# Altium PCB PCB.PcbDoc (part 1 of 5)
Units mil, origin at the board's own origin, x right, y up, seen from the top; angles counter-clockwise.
Board outline 6700 x 6500 mil, 2 copper layers (Top Layer, Bottom Layer); 203 components, 278 nets, 1296 pads, 461 vias.
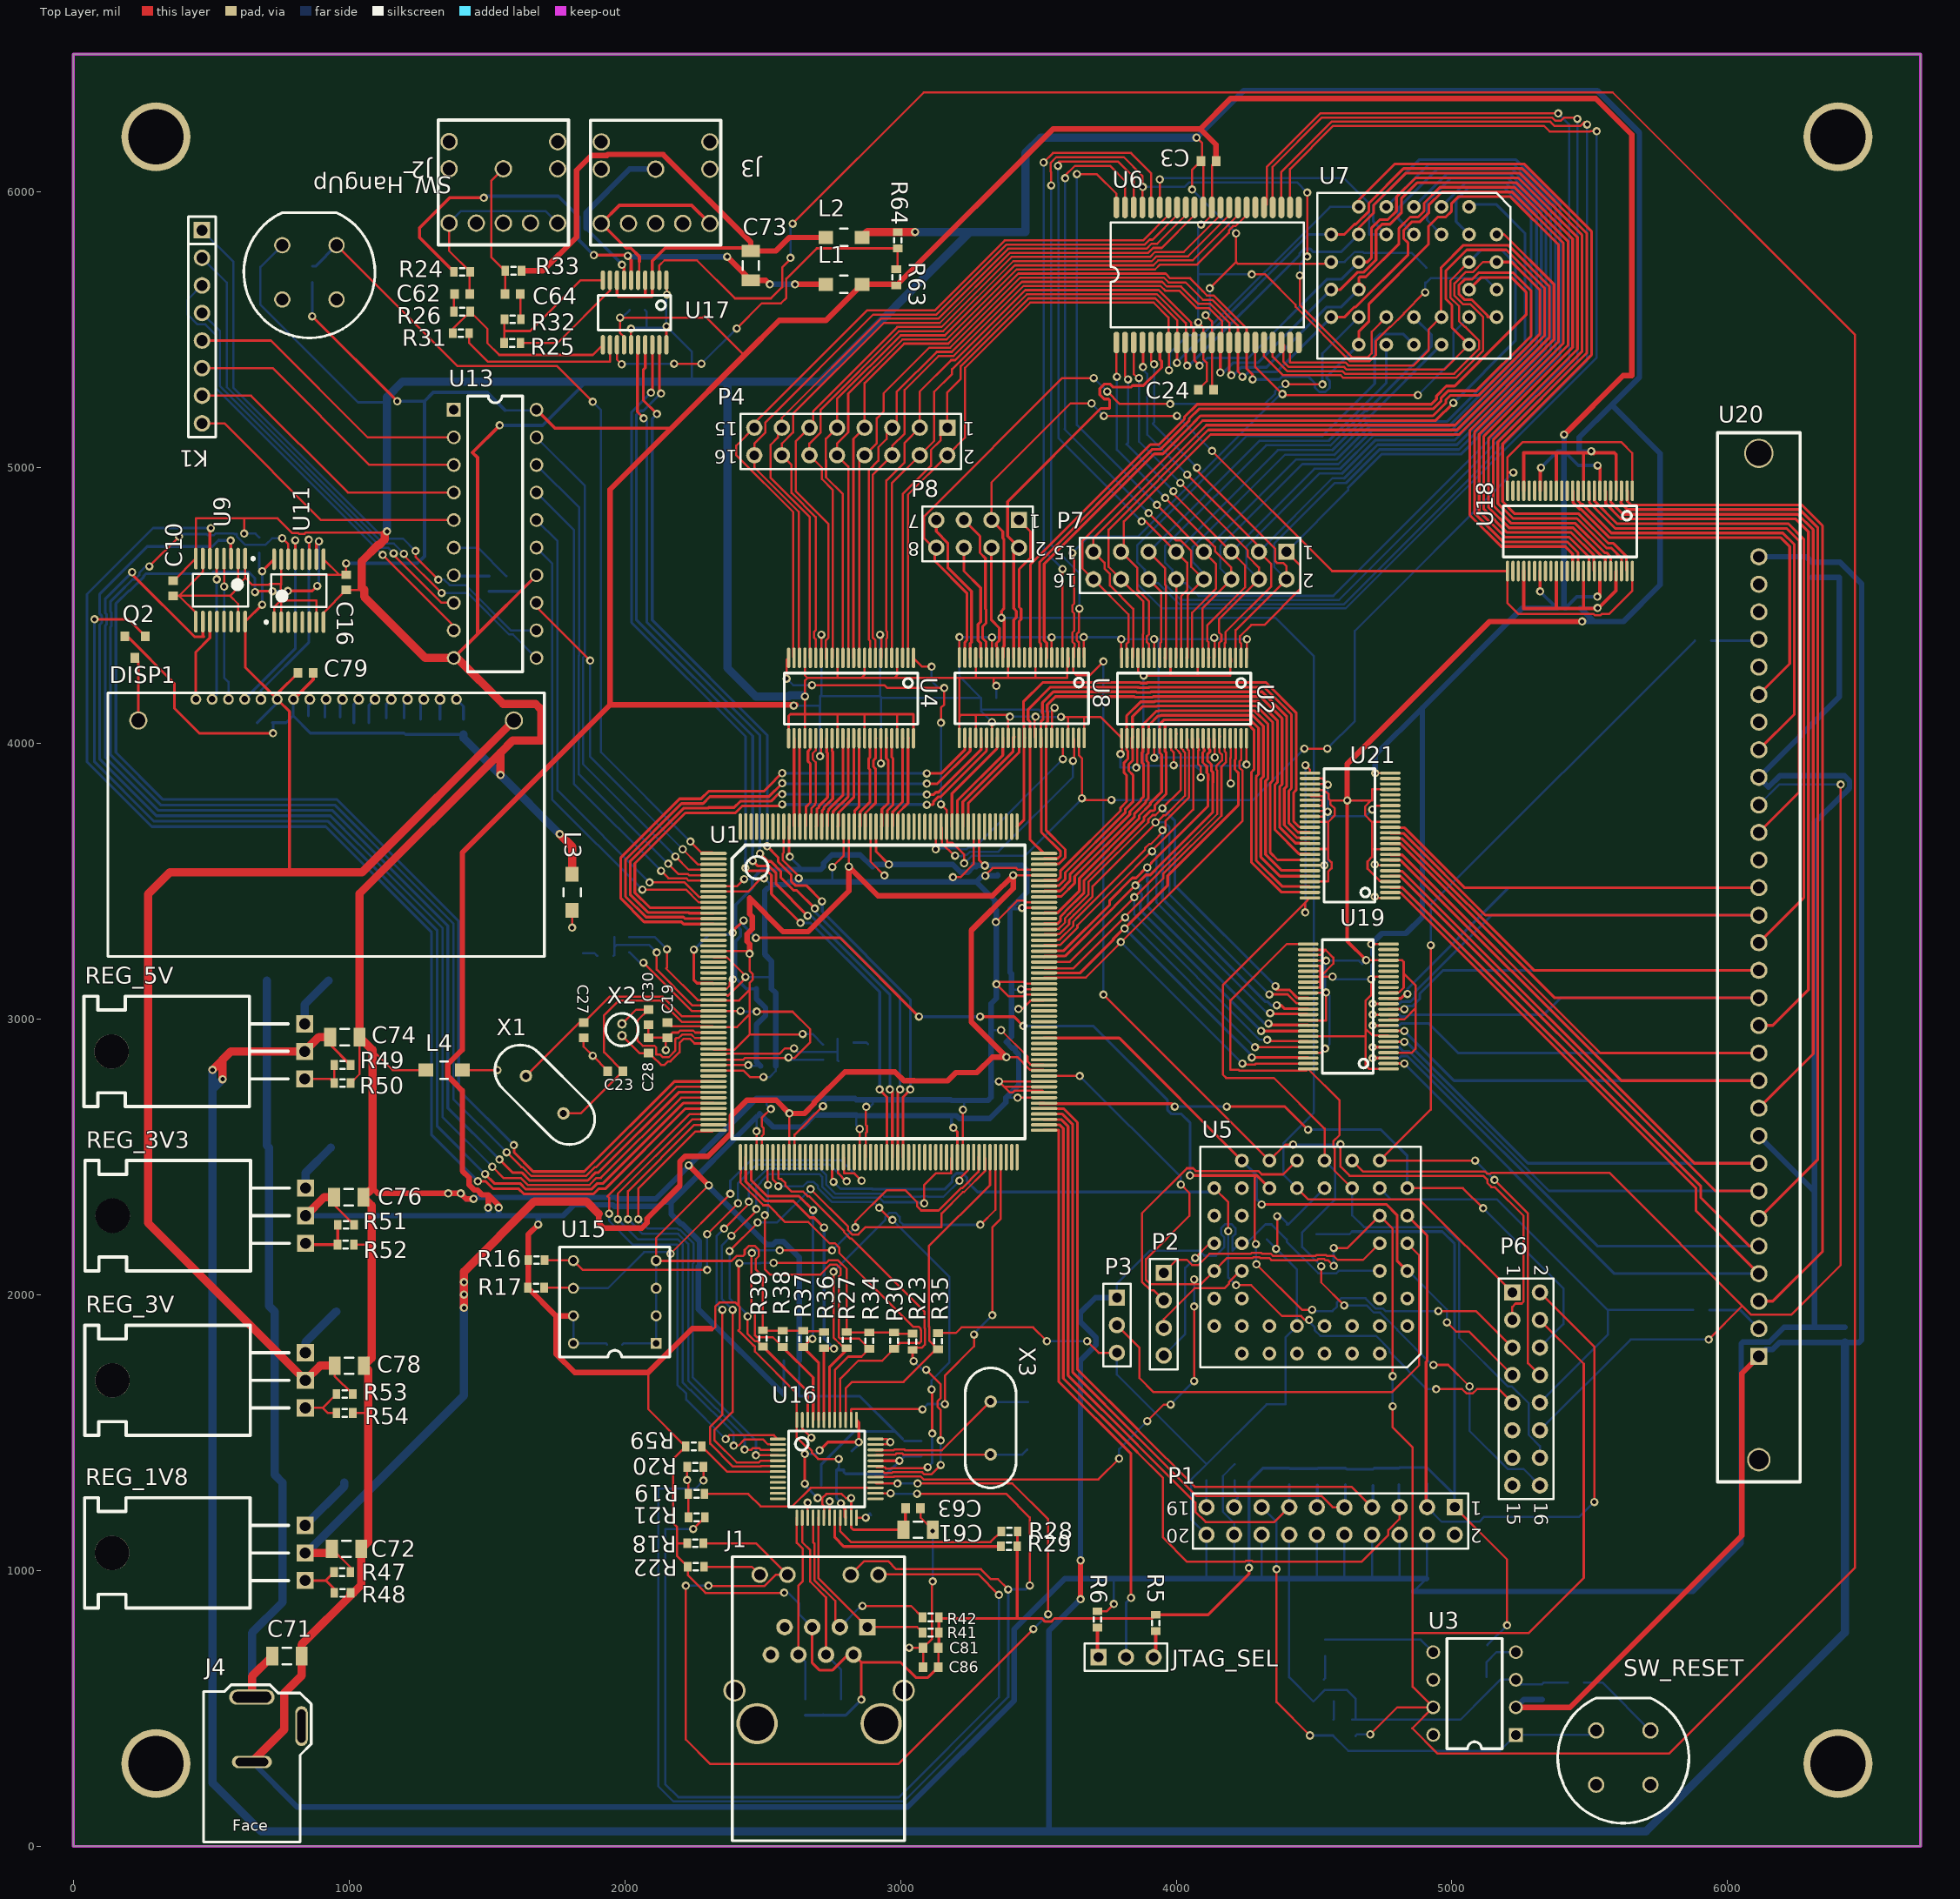
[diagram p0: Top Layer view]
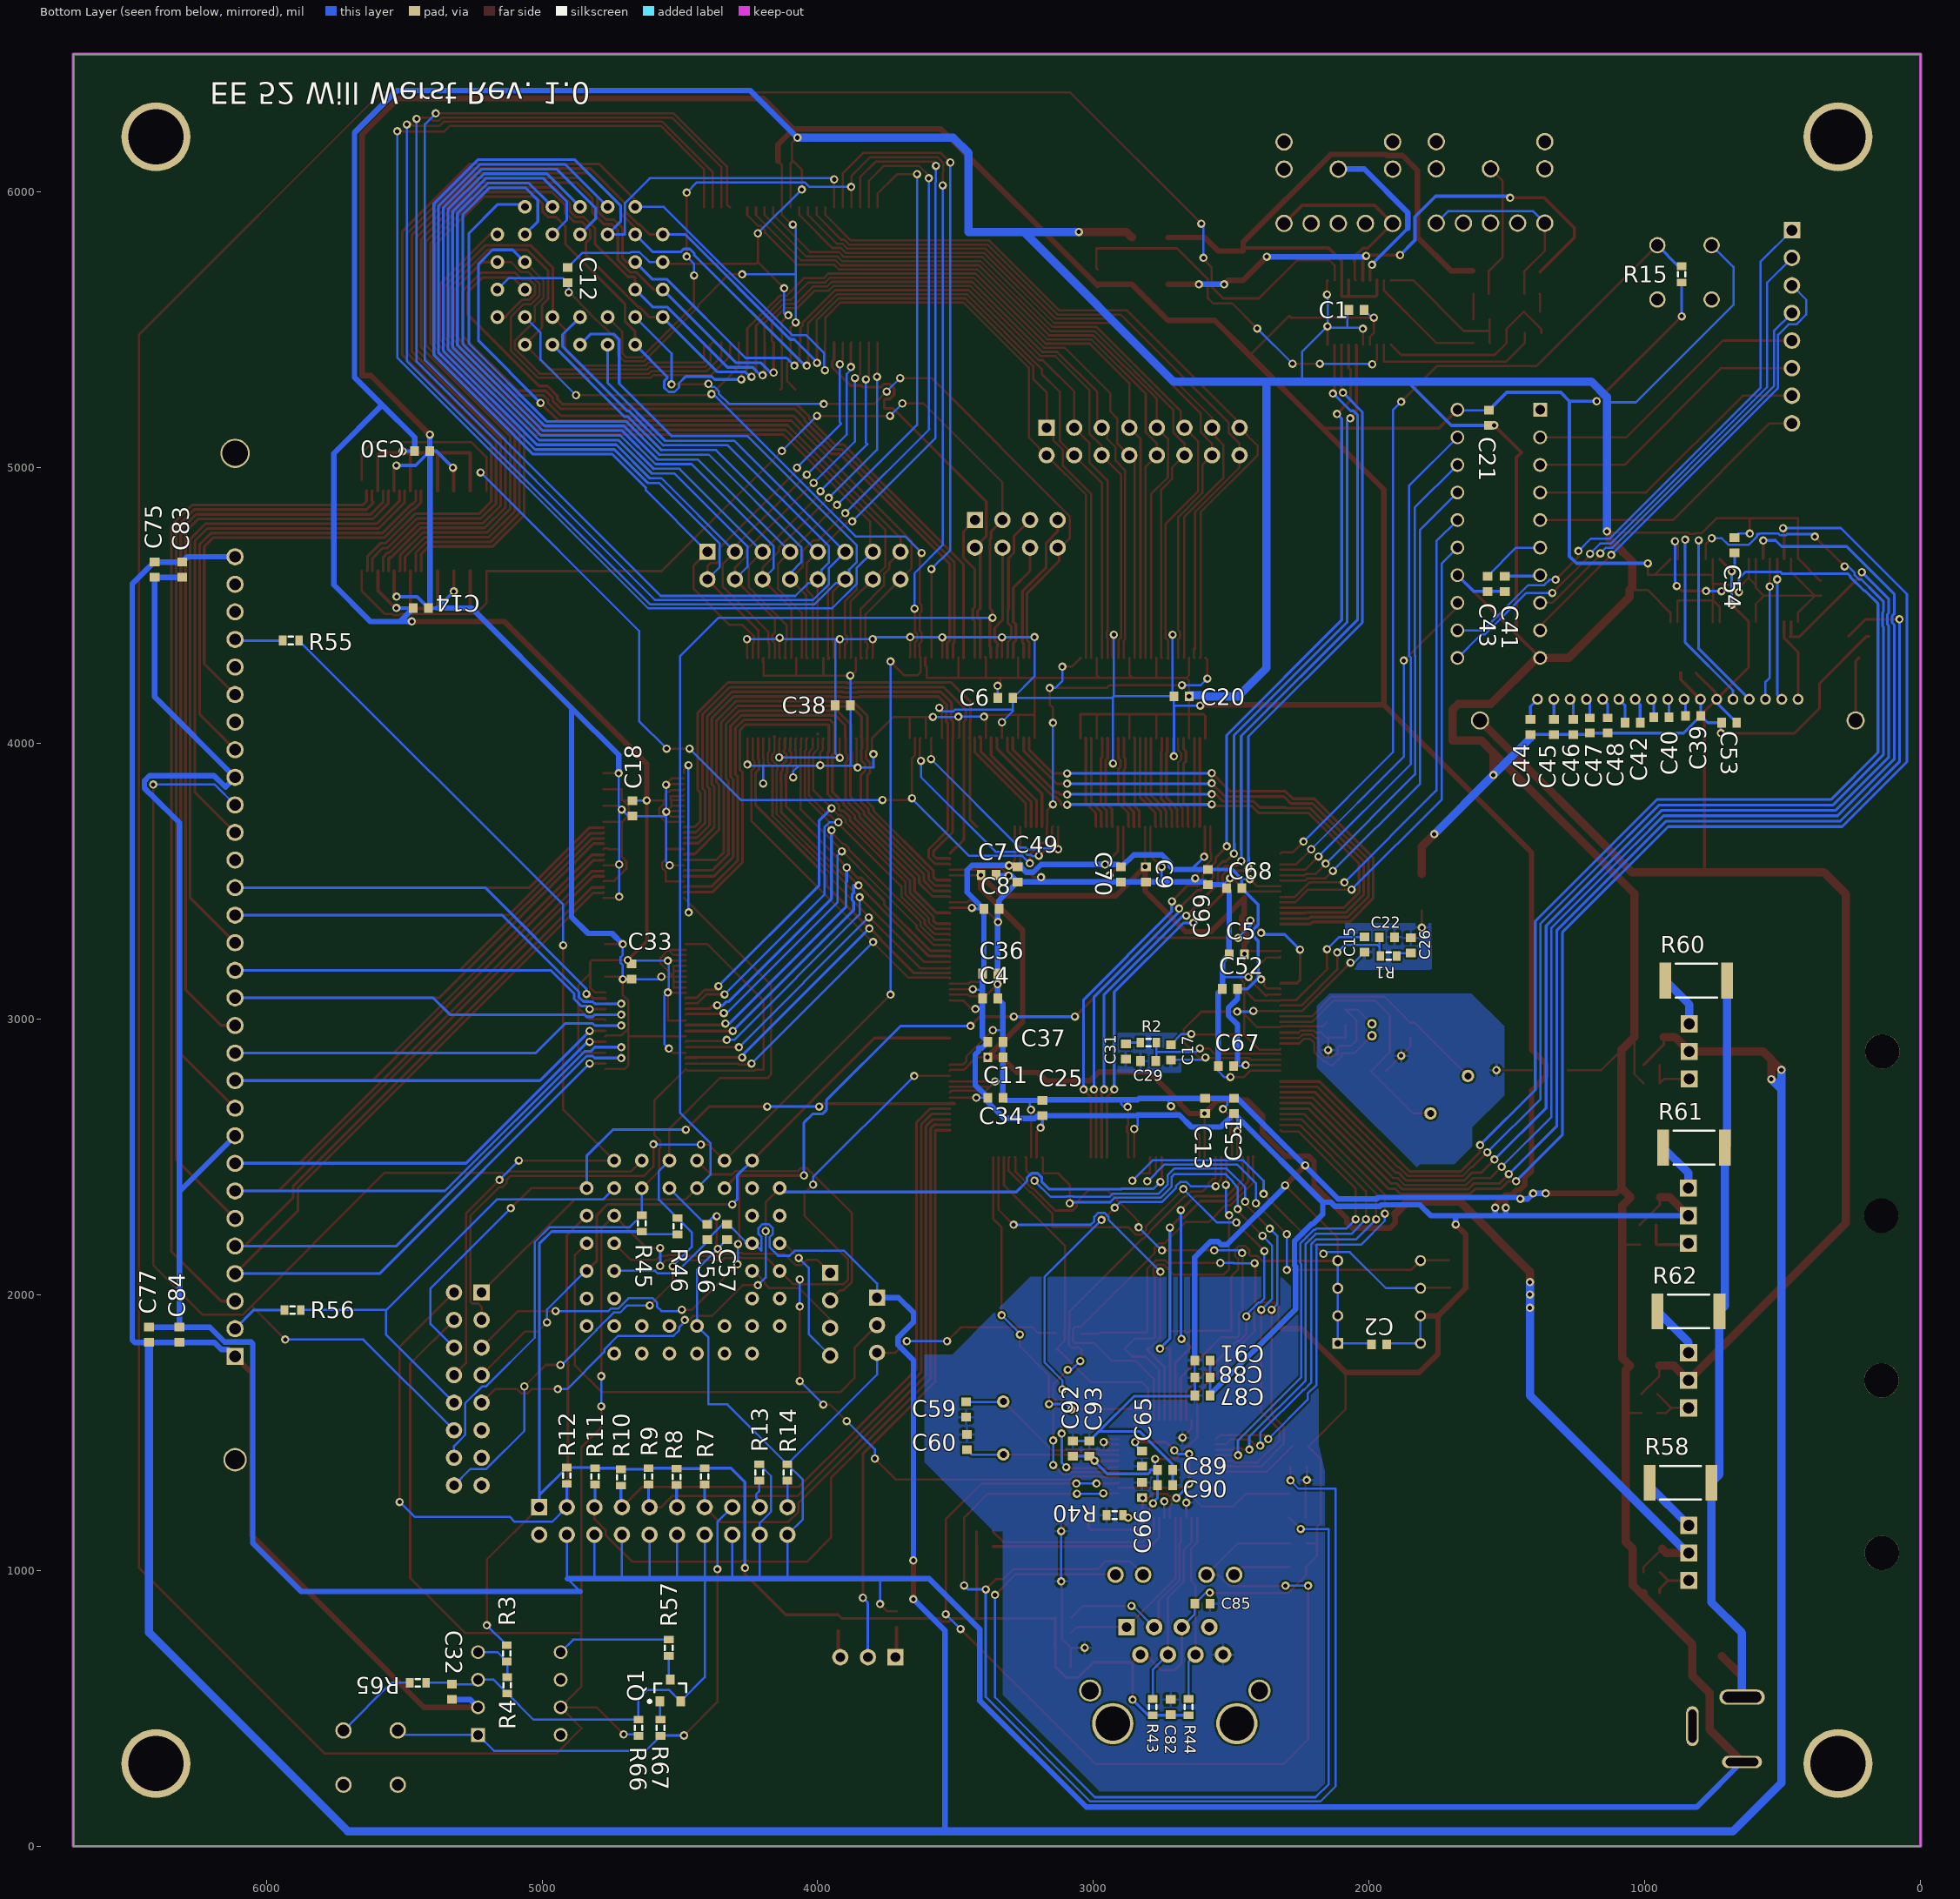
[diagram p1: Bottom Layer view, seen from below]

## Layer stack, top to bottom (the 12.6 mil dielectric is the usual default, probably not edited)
Top Solder: solder mask 0.4, Solder Resist, Dk 3.5
Top Layer: signal copper 1.4
Dielectric 1: dielectric 12.6, FR-4, Dk 4.8
Bottom Layer: signal copper 1.4
Bottom Solder: solder mask 0.4, Solder Resist, Dk 3.5

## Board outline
0,0 0,6500 6700,6500 6700,0

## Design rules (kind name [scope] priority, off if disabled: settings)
Clearance [All] p1: gap=7 ignorepadtopadclearanceinfootprint=FALSE except(0: Arc-Hole Track-Hole SMDPad-Hole THPad-Hole Via-Hole Fill-Hole Poly-Hole Region-Hole Text-Hole)
HoleSize [All] p1: absolutevalues=TRUE maxlimit=250 minlimit=10 maxpercent=80.000 minpercent=20.000
MinimumAnnularRing [All] p1: minimumring=7
MinimumSolderMaskSliver [All] p1 off: minsoldermaskwidth=3
PlaneConnect [All] p1: planeconnectstyle=Relief reliefexpansion=15 reliefentries=4 reliefconductorwidth=10 reliefairgap=10
PolygonConnect [All] p1: connectstyle=Relief reliefconductorwidth=10 reliefentries=4 polygonreliefangle="90 Angle" airgapwidth=10
RoutingCorners [All] p1: cornerstyle=45-Degree minsetback=10 maxsetback=100
RoutingTopology [All] p1: topology=Daisy_Balanced
RoutingVias [All] p1: holewidth=16 width=30 viastyle="Through Hole" minholewidth=16 minwidth=30 maxholewidth=28 maxwidth=50
SilkToSilkClearance [All] p1: silktosilkclearance=6
SilkToSolderMaskClearance [IsPad] p1 off: minsilkscreentomaskgap=3 clearancetoexposedcopper=TRUE
SolderMaskExpansion [All] p1: expansion=2.5
Width [All] p1: maxlimit=30 minlimit=7 preferedwidth=8
23 further rules are at their usual default settings.

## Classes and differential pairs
net class A_3V3_BUF_[0..19]: A_3V3_BUF_0 A_3V3_BUF_1 A_3V3_BUF_2 A_3V3_BUF_3 A_3V3_BUF_4 A_3V3_BUF_5 A_3V3_BUF_6 A_3V3_BUF_7 A_3V3_BUF_8 A_3V3_BUF_9 A_3V3_BUF_10 A_3V3_BUF_11 A_3V3_BUF_12 A_3V3_BUF_13 A_3V3_BUF_14 A_3V3_BUF_15 A_3V3_BUF_16 A_3V3_BUF_17 A_3V3_BUF_18 A_3V3_BUF_19
net class ADDR[16..19]: ADDR0 ADDR1 ADDR2 ADDR3 ADDR4 ADDR5 ADDR6 ADDR7 ADDR8 ADDR9 ADDR10 ADDR11 ADDR12 ADDR13 ADDR14 ADDR15 ADDR16 ADDR17 ADDR18 ADDR19
net class D_3V3B[0..15]: D_3V3B0 D_3V3B1 D_3V3B2 D_3V3B3 D_3V3B4 D_3V3B5 D_3V3B6 D_3V3B7 D_3V3B8 D_3V3B9 D_3V3B10 D_3V3B11 D_3V3B12 D_3V3B13 D_3V3B14 D_3V3B15
net class DATA[0..15]: DATA0 DATA1 DATA2 DATA3 DATA4 DATA5 DATA6 DATA7 DATA8 DATA9 DATA10 DATA11 DATA12 DATA13 DATA14 DATA15
net class NCS3V3B[0..7]: NCS3V3B0 NCS3V3B1 NCS3V3B2 NCS3V3B3 NCS3V3B4 NCS3V3B5 NCS3V3B6 NCS3V3B7
net class NCS[4..7]: NCS0 NCS1 NCS2 NCS3 NCS4 NCS5 NCS6 NCS7

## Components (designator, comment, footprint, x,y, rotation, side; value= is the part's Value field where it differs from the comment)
C1 "" 1608[0603] 2046,5572 r0 bottom value=0.1uF
C2 "" 1608[0603] 1964,1820 r0 bottom value=0.1uF
C3 "" 1608[0603] 4117,6112 r180 top value=0.1uF
C4 "" 1608[0603] 3375,3075 r180 bottom value=0.1uF
C5 "" 1608[0603] 2480,3235 r180 bottom value=0.1uF
C6 "" 1608[0603] 3320,4165 r0 bottom value=0.1uF
C7 "" 1608[0603] 3380,3523 r0 bottom value=0.1uF
C8 "" 1608[0603] 3370,3400 r180 bottom value=0.1uF
C9 "" 1608[0603] 2810,3525 r90 bottom value=0.1uF
C10 "" 1608[0603] 362,4563 r90 top value=0.1uF
C11 "" 1608[0603] 3356,2861 r0 bottom value=0.1uF
C12 "" 1608[0603] 4907,5698.44 r90 bottom value=0.1uF
C13 "" 1608[0603] 2595,2685 r270 bottom value=0.1uF
C14 "" 1608[0603] 5439,4491 r0 bottom value=0.1uF
C15 "" 1608[0603] 2017,3270.56 r90 bottom value=0.1uF
C16 "" 1608[0603] 990,4584 r270 top value=0.1uF
C17 "" 1608[0603] 2719,2880 r90 bottom value=0.1uF
C18 "" 1608[0603] 4672,3764 r90 bottom value=0.1uF
C19 "" 1608[0603] 2155,2960 r90 top value=0.1uF
C20 "" 1608[0603] 2681,4171 r180 bottom value=0.1uF
C21 "" 1608[0603] 1566,5181 r270 bottom value=0.1uF
C22 "" 1608[0603] 1935.67,3297 r180 bottom value=1nF
C23 "" 1608[0603] 1966,2811 r180 top value=30pF
C24 "" 1608[0603] 4108,5283 r0 top value=0.1uF
C25 "" 1608[0603] 3185,2677.44 r90 bottom value=0.1uF
C26 "" 1608[0603] 1849,3267 r90 bottom value=10nF
C27 "" 1608[0603] 1851,2960 r270 top value=30pF
C28 "" 1608[0603] 2086,2904 r90 top value=16pF
C29 "" 1608[0603] 2802,2848 r0 bottom value=1nF
C30 "" 1608[0603] 2086,3007 r270 top value=16pF
C31 "" 1608[0603] 2882,2882 r270 bottom value=10nF
C32 "" 1608[0603] 5327,560 r90 bottom value=0.1uF
C33 "" 1608[0603] 4675,3172.44 r90 bottom value=0.1uF
C34 "" 1608[0603] 3355,2715 r180 bottom value=0.1uF
C36 "" 1608[0603] 3375,3165 r180 bottom value=0.1uF
C37 "" 1608[0603] 3356,2917 r180 bottom value=0.1uF
C38 "" 1608[0603] 3909,4138 r180 bottom value=0.1uF
C39 "" 1608[0603] 825,4100 r180 bottom value=1uF
C40 "" 1608[0603] 940,4095 r180 bottom value=1uF
C41 "" 1608[0603] 1508,4579 r270 bottom value=1uF
C42 "" 1608[0603] 1045,4075 r180 bottom value=1uF
C43 "" 1608[0603] 1571,4579 r270 bottom value=0.1uF
C44 "" 1608[0603] 1415,4060 r90 bottom value=1uF
C45 "" 1608[0603] 1330,4060 r90 bottom value=1uF
C46 "" 1608[0603] 1260,4060 r90 bottom value=1uF
C47 "" 1608[0603] 1200,4065 r90 bottom value=1uF
C48 "" 1608[0603] 1135,4065 r90 bottom value=1uF
C49 "" 1608[0603] 3275,3525 r270 bottom value=0.1uF
C50 "" 1608[0603] 5434,5060 r0 bottom value=0.1uF
C51 "" 1608[0603] 2490,2685 r90 bottom value=0.1uF
C52 "" 1608[0603] 2505,3110 r0 bottom value=0.1uF
C53 "" 1608[0603] 695,4075 r0 bottom value=0.1uF
C54 "" 1608[0603] 675,4719 r90 bottom value=0.1uF
C56 "" 1608[0603] 4401,2228 r90 bottom value=0.1uF
C57 "" 1608[0603] 4329,2228 r270 bottom value=0.1uF
C59 "" 1608[0603] 3462,1584 r270 bottom value=30pF
C60 "" 1608[0603] 3459,1466 r90 bottom value=30pF
C61 "Tant" C1206 3064,1148 r0 top value=10uF
C62 "" 1608[0603] 1410,5630 r180 top value=0.22uF
C63 "" 1608[0603] 3045.56,1226 r0 top value=0.1uF
C64 "" 1608[0603] 1594,5630 r0 top value=0.22uF
C65 "" 1608[0603] 2824,1406 r270 bottom value=0.1uF
C66 "" 1608[0603] 2824,1292 r90 bottom value=0.1uF
C67 "" 1608[0603] 2520,2830 r0 bottom value=0.1uF
C68 "" 1608[0603] 2490,3475 r0 bottom value=0.1uF
C69 "" 1608[0603] 2585,3515 r270 bottom value=0.1uF
C70 "" 1608[0603] 2900,3525 r270 bottom value=0.1uF
C71 "" C1206 775,690 r180 top value=10uF
C72 "" C1206 991,1079 r180 top value=10uF
C73 "" C1206 2457,5733 r270 top value=10uF
C74 "" C1206 985,2935 r180 top value=10uF
C75 "" 1608[0603] 6405,4630 r270 bottom value=1uF
C76 "" C1206 999,2354 r180 top value=10uF
C77 "" 1608[0603] 6425,1855 r90 bottom value=1uF
C78 "" C1206 1001,1743 r180 top value=10uF
C79 "" 1608[0603] 843,4256 r180 top value=1uF
C81 "" 1608[0603] 3110,720 r180 top value=0.1uF
C82 "" 1608[0603] 2720,505 r90 bottom value=0.1uF
C83 "" 1608[0603] 6305,4630 r270 bottom value=0.01uF
C84 "" 1608[0603] 6315,1855 r90 bottom value=0.01uF
C85 "" 1608[0603] 2605,880 r180 bottom value=0.1uF
C86 "" 1608[0603] 3110,650 r180 top value=0.1uF
C87 "" 1608[0603] 2605,1635 r0 bottom value=0.1uF
C88 "" 1608[0603] 2605,1700 r0 bottom value=0.01uF
C89 "" 1608[0603] 2740,1365 r180 bottom value=0.1uF
C90 "" 1608[0603] 2740,1310 r180 bottom value=0.1uF
C91 "" 1608[0603] 2605,1762 r0 bottom value=1uF
C92 "" 1608[0603] 3075,1442.44 r90 bottom value=0.1uF
C93 "" 1608[0603] 3015,1442.44 r90 bottom value=0.01uF
DISP1 "Newhaven Display NHD-C12832A1Z-FSW-FBW-3V3" PCB-1539121-1 917.06,4160 r180 top locked
J1 "SI-50170" SI51070 2530,695 r0 top
J2 "Speaker" SJ1-352 1363.15,5887.15 r90 top locked
J3 "Microphone" SJ1-352 1915.15,5886 r90 top locked
J4 "Power Connector" EJ508A 648,16 r0 top locked
JTAG_SEL "Header 3" HDR1X3 3718,686 r0 top
K1 "KEYPAD4X4" SIP8 467,5861 r270 top
L1 "742792116" SMD-1206 2795,5665 r0 top
L2 "742792116" SMD-1206 2795,5835 r0 top
L3 "742792116" SMD-1206 1809,3460 r90 top
L4 "742792116" SMD-1206 1345,2815 r180 top
P1 "Header 10X2" HDR2X10 5010,1230 r180 top locked
P2 "Header 4" HDR1X4 3955,2080 r270 top
P3 "Header 3" HDR1X3 3785,1990 r270 top
P4 "Header 8X2" HDR2X8 3170,5145 r180 top locked
P6 "Header 8X2" HDR2X8 5219,2009 r270 top
P7 "Header 8X2" HDR2X8 4400,4695 r180 top locked
P8 "Header 4X2" HDR2X4 3430,4810 r180 top locked
Q1 "MMBFJ175LT1" ONSC-SOT-23-3-318-08_V 4535,565 r90 bottom
Q2 "DMG3420U" SOT23 224,4310 r180 top
R1 "Res3" J1-0603 1930,3229 r0 bottom value=909
R2 "Res3" J1-0603 2801,2915 r180 bottom value=1000
R3 "Res3" J1-0603 5128,700 r90 bottom value=12K
R4 "Res3" J1-0603 5126,584 r90 bottom value=10K
R5 "Res3" J1-0603 3926,810.47 r90 top value=10K
R6 "Res3" J1-0603 3714,822.47 r90 top value=10K
R7 "Res3" J1-0603 4410,1342 r90 bottom value=10K
R8 "Res3" J1-0603 4512,1340 r90 bottom value=10K
R9 "Res3" J1-0603 4614,1342 r90 bottom value=10K
R10 "Res3" J1-0603 4714,1338 r90 bottom value=10K
R11 "Res3" J1-0603 4808,1342 r90 bottom value=10K
R12 "Res3" J1-0603 4910,1344 r90 bottom value=10K
R13 "Res3" J1-0603 4212,1356 r90 bottom value=10K
R14 "Res3" J1-0603 4110,1356 r90 bottom value=10K
R15 "Res3" J1-0603 867,5701 r270 bottom value=10K
R16 "Res3" J1-0603 1680,2126 r180 top value=2.2k
R17 "Res3" J1-0603 1678,2026 r180 top value=2.2k
R18 "Res3" J1-0603 2256,1099 r0 top value=2.2K
R19 "Res3" J1-0603 2260,1278 r0 top value=2.2K
R20 "Res3" J1-0603 2256,1376 r0 top value=2.2K
R21 "Res3" J1-0603 2261,1193 r0 top value=220
R22 "Res3" J1-0603 2258,1014 r0 top value=220
R23 "Res3" J1-0603 3044,1830 r270 top value=1.5K
R24 "Res3" J1-0603 1410,5710 r180 top value=2K
R25 "Res3" J1-0603 1592,5452 r0 top value=510K
R26 "Res3" J1-0603 1410,5566 r0 top value=34K
R27 "Res3" J1-0603 2805,1836 r90 top value=2.2K
R28 "Res3" J1-0603 3395,1142 r180 top value=2.2K
R29 "Res3" J1-0603 3394,1088 r180 top value=2.2K
R30 "Res3" J1-0603 2977,1834 r90 top value=2.2K
R31 "Res3" J1-0603 1406,5488 r0 top value=510K
R32 "Res3" J1-0603 1593.53,5538 r180 top value=34K
R33 "Res3" J1-0603 1596,5714 r180 top value=2K
R34 "Res3" J1-0603 2887,1834 r90 top value=2.2K
R35 "Res3" J1-0603 3136,1832 r90 top value=2.2K
R36 "Res3" J1-0603 2723,1836 r270 top value=2.2K
R37 "Res3" J1-0603 2647,1840 r270 top value=2.2K
R38 "Res3" J1-0603 2573,1840 r270 top value=2.2K
R39 "Res3" J1-0603 2501,1842 r90 top value=2.2K
R40 "Res3" J1-0603 2923,1201 r0 bottom value=4.87K
R41 "Res3" J1-0603 3110,775 r0 top value=49.9
R42 "Res3" J1-0603 3110,830 r0 top value=49.9
R43 "Res3" J1-0603 2785,505 r270 bottom value=49.9
R44 "Res3" J1-0603 2655,505 r270 bottom value=49.9
R45 "Res3" J1-0603 4638,2259 r270 bottom value=10K
R46 "Res3" J1-0603 4509,2249 r270 bottom value=10K
R47 "Res3" J1-0603 975.53,994 r0 top value=120
R48 "Res3" J1-0603 976,919 r180 top value=52.3
R49 "Res3" J1-0603 976,2834 r0 top value=120
R50 "Res3" J1-0603 976,2768 r180 top value=365
R51 "Res3" J1-0603 989,2254 r0 top value=120
R52 "Res3" J1-0603 988,2182 r180 top value=196
R53 "Res3" J1-0603 984,1640 r0 top value=120
R54 "Res3" J1-0603 984,1572 r180 top value=169
R55 "Res3" J1-0603 5911,4373 r180 bottom value=0
R56 "Res3" J1-0603 5904.53,1945 r180 bottom value=0
R57 "Res3" J1-0603 4540,720 r270 bottom value=0
R58 "1W" RESC6332 871,1319 r0 bottom value=2.2
R59 "Res3" J1-0603 2250.47,1450 r180 top value=2.2K
R60 "1W" RESC6332 814,3140 r180 bottom value=2.2
R61 "1W" RESC6332 822,2534 r180 bottom value=2.2
R62 "1W" RESC6332 842,1940 r180 bottom value=2.2
R63 "Res3" J1-0603 2985,5690 r270 top value=2.2k
R64 "Res3" J1-0603 2990,5825 r270 top value=2.2k
R65 "Res3" J1-0603 5450,593 r180 bottom value=1k
R66 "Res3" J1-0603 4650,430 r90 bottom value=100k
R67 "Res3" J1-0603 4570,430 r90 bottom value=1k
REG_1V8 "LM1086-ADJ" TO-220 841,964 r90 top locked
REG_3V "LM1086-ADJ" TO-220 842,1590 r90 top locked
REG_3V3 "LM1086-ADJ" TO-220 843,2187 r90 top locked
REG_5V "LM1086-ADJ" TO-220 839,2783 r90 top locked
SW_HangUp "KS01Q01" KS01Q01 955,5806.85 r0 top (schematic designator SW_HANGUP)
SW_RESET "KS01Q01" KS01Q01 5720,420 r0 top
U1 "AT91RM9200" PQFP208 2755,3195 r0 top locked
U2 "74LVT16245" TSSOP48 4254.96,4310 r180 top locked
U3 "MAX705" DIP8 5232,404 r180 top
U4 "74LVT16245" TSSOP48 3047.16,4310 r180 top
U5 "ISPLSI1016E" PLCCS44 4838,1787 r180 top locked
U6 "SRAM IDT71V016" SSOP44.400 3783.04,5454 r90 top locked
U7 "ROM 29LV040" PLCCS32 5162,6046 r270 top locked
U8 "74LVT16245" TSSOP48 3666.53,4311.34 r180 top locked
U9 "TI-CD40109B-16" TI-PW16_M 534,4556 r270 top
U11 "TI-CD40109B-16" TI-PW16_M 818,4554 r90 top
U13 "MM74C923" DIP20 1380,5210 r0 top locked
U15 "24AA32" DIPS8 2114,1824 r180 top locked
U16 "DP83848" LQFP48 2531.68,1477.1 r0 top locked
U17 "TLV320AIC1106" PSOP20 2151.13,5680 r180 top locked
U18 "74LVT16245" TSSOP48 5654.33,4916.34 r180 top locked
U19 "74LVT16245" TSSOP48 4770,2819.41 r90 top
U20 "DRAM1MX8" SIMM30 6113,1777 r90 top locked
U21 "74LVT16245" TSSOP48 4776.34,3439.73 r90 top locked
X1 "20 MHz" HC-49U 1642,2794 r315 top
X2 "32.768 kHz" FX-3 1990,2983 r270 top
X3 "25 MHz" HC-49U 3327,1421 r90 top

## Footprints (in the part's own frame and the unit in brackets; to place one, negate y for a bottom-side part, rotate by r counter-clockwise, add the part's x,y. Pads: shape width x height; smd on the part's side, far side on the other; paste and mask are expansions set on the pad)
1608[0603] [mm] "Chip Capacitor, Body 1.6x0.8mm, IPC High Density"
  rect 0.8x0.9 smd: 1(-0.7,0) 2(0.7,0)
  body extent -0.87,-0.48 0.87,0.48, height 1.3
C1206 [mm] "Chip Capacitor, Body 3.2x1.6mm, IPC High Density"
  rect 1.1x1.7 smd: 1(-1.35,0) 2(1.35,0)
  silkscreen extent -0.4,-0.75 0.4,0.75, body extent -1.7,-0.9 1.7,0.9, height 1.3
DIP8 [mil]
  rect 50x50 hole 35: 1(0,0)
  round 50 hole 35: 2(0,-100) 3(0,-200) 4(0,-300) 5(300,-300) 6(300,-200) 7(300,-100) 8(300,0)
  silkscreen extent 50,-350 250,50
DIP20 [mil]
  rect 50x50 hole 35: 1(0,0)
  round 50 hole 35: 2(0,-100) 3(0,-200) 4(0,-300) 5(0,-400) 6(0,-500) 7(0,-600) 8(0,-700) 9(0,-800) 10(0,-900) 11(300,-900) 12(300,-800) 13(300,-700) 14(300,-600) 15(300,-500) 16(300,-400) 17(300,-300) 18(300,-200) 19(300,-100) 20(300,0)
  silkscreen extent 50,-950 250,50
DIPS8 [mil]
  rect 40x40 hole 25: 1(0,0)
  round 40 hole 25: 2(0,-100) 3(0,-200) 4(0,-300) 5(300,-300) 6(300,-200) 7(300,-100) 8(300,0)
  silkscreen extent -50,-350 350,50
EJ508A [mil]
  oval 145x45 hole 29.92 slot 118.11 at 0 deg: GND(0,290)
  oval 45x145 hole 29.92 slot 120.08 at 90 deg: SWITCH(180,420)
  oval 165x55 hole 40.16 slot 140.16 at 0 deg: VCC(0,525)
  silkscreen extent -175,0 215,570
FX-3 [mil]
  round 34 hole 20: 1(0,0) 2(43,0)
  silkscreen extent -38,-59 80,59
HC-49U [mil]
  round 45 hole 25: 1(0,0) 2(192,0)
  silkscreen extent -121,-92 314,92
HDR1X3 [mm] "Connector; Header; 3 Position"
  rect 1.5x1.5 hole 0.9: 1(0,0)
  round 1.5 hole 0.9: 2(2.54,0) 3(5.08,0)
  silkscreen extent -1.27,-1.27 6.35,1.27
HDR1X4 [mm] "Connector; Header; 4 Position"
  rect 1.5x1.5 hole 0.9: 1(0,0)
  round 1.5 hole 0.9: 2(2.54,0) 3(5.08,0) 4(7.62,0)
  silkscreen extent -1.27,-1.27 8.89,1.27
HDR2X4 [mm] "Connector; Header; 4x2 Position"
  rect 1.5x1.5 hole 0.9: 1(0,0)
  round 1.5 hole 0.9: 2(0,2.54) 3(2.54,0) 4(2.54,2.54) 5(5.08,0) 6(5.08,2.54) 7(7.62,0) 8(7.62,2.54)
  silkscreen extent -1.27,-1.27 8.89,3.81
HDR2X8 [mm] "Connector; Header; 8x2 Position"
  rect 1.5x1.5 hole 0.9: 1(0,0)
  round 1.5 hole 0.9: 2(0,2.54) 3(2.54,0) 4(2.54,2.54) 5(5.08,0) 6(5.08,2.54) 7(7.62,0) 8(7.62,2.54) 9(10.16,0) 10(10.16,2.54) 11(12.7,0) 12(12.7,2.54) 13(15.24,0) 14(15.24,2.54) 15(17.78,0) 16(17.78,2.54)
  silkscreen extent -1.27,-1.27 19.05,3.81
HDR2X10 [mm] "Connector; Header; 10x2 Position"
  rect 1.5x1.5 hole 0.9: 1(0,0)
  round 1.5 hole 0.9: 2(0,2.54) 3(2.54,0) 4(2.54,2.54) 5(5.08,0) 6(5.08,2.54) 7(7.62,0) 8(7.62,2.54) 9(10.16,0) 10(10.16,2.54) 11(12.7,0) 12(12.7,2.54) 13(15.24,0) 14(15.24,2.54) 15(17.78,0) 16(17.78,2.54) 17(20.32,0) 18(20.32,2.54) 19(22.86,0) 20(22.86,2.54)
  silkscreen extent -1.27,-1.27 24.13,3.81
J1-0603 [mm] "Chip Resistor, Body 1.6x0.8mm, IPC High Density"
  rect 0.7x0.9 smd: 1(-0.75,0) 2(0.75,0)
  silkscreen extent -0.2,-0.35 0.2,0.35, body extent -0.85,-0.48 0.85,0.48, height 0.9
KS01Q01 [mm] "Normally Open Switch"
  round 1.5 hole 1.1 mask+0.04: 1(0,0) 2(-5,0) 3(0,-5) 4(-5,-5)
  silkscreen extent -8.54,-8.54 3.54,3
LQFP48 [mm]
  oval 1.5x0.25 smd: 1(0.6,0) 2(0.6,-0.5) 3(0.6,-1) 4(0.6,-1.5) 5(0.6,-2) 6(0.6,-2.5) 7(0.6,-3) 8(0.6,-3.5) 9(0.6,-4) 10(0.6,-4.5) 11(0.6,-5) 12(0.6,-5.5) 25(9.6,-5.5) 26(9.6,-5) 27(9.6,-4.5) 28(9.6,-4) 29(9.6,-3.5) 30(9.6,-3) 31(9.6,-2.5) 32(9.6,-2) 33(9.6,-1.5) 34(9.6,-1) 35(9.6,-0.5) 36(9.6,0)
  oval 0.25x1.5 smd: 13(2.35,-7.25) 14(2.85,-7.25) 15(3.35,-7.25) 16(3.85,-7.25) 17(4.35,-7.25) 18(4.85,-7.25) 19(5.35,-7.25) 20(5.85,-7.25) 21(6.35,-7.25) 22(6.85,-7.25) 23(7.35,-7.25) 24(7.85,-7.25) 37(7.85,1.75) 38(7.35,1.75) 39(6.85,1.75) 40(6.35,1.75) 41(5.85,1.75) 42(5.35,1.75) 43(4.85,1.75) 44(4.35,1.75) 45(3.85,1.75) 46(3.35,1.75) 47(2.85,1.75) 48(2.35,1.75)
  silkscreen extent 1.6,-6.25 8.6,0.75
ONSC-SOT-23-3-318-08_V [mm] "SOT23, 3-Leads, Body 2.92x1.3mm, Pitch 0.95mm"
  rect 0.9x0.8 smd: 1(-1,0.95) 2(-1,-0.95) 3(1,0)
  silkscreen extent -1.12,-1.46 0.65,2.03, body extent -0.65,-1.46 0.65,1.46, height 1.11
PCB-1539121-1 [mm]
  round 1 hole 0.6: 1(-12,0) 2(-10.5,0) 3(-9,0) 4(-7.5,0) 5(-6,0) 6(-4.5,0) 7(-3,0) 8(-1.5,0) 9(0,0) 10(1.5,0) 11(3,0) 12(4.5,0) 13(6,0) 14(7.5,0) 15(9,0) 16(10.5,0) 17(12,0)
  round 1.676 hole 1.3: 18(-17.3,1.95) 19(17.3,1.95)
  silkscreen extent -20.1,-0.6 20.1,23.7, body extent -20.1,-0.6 20.1,23.7, height 4.9
PLCCS32 [mil]
  round 50 hole 28: 1(400,-100) 2(300,0) 3(300,-100) 4(200,0) 5(100,-100) 6(200,-100) 7(100,-200) 8(200,-200) 9(100,-300) 10(200,-300) 11(100,-400) 12(200,-400) 13(100,-500) 14(200,-600) 15(200,-500) 16(300,-600) 17(300,-500) 18(400,-600) 19(400,-500) 20(500,-600) 21(600,-500) 22(500,-500) 23(600,-400) 24(500,-400) 25(600,-300) 26(500,-300) 27(600,-200) 28(500,-200) 29(600,-100) 30(500,0) 31(500,-100) 32(400,0)
  silkscreen extent 50,-650 650,50
PLCCS44 [mil]
  round 50 hole 28: 1(400,-100) 2(300,0) 3(300,-100) 4(200,0) 5(200,-100) 6(100,0) 7(0,-100) 8(100,-100) 9(0,-200) 10(100,-200) 11(0,-300) 12(100,-300) 13(0,-400) 14(100,-400) 15(0,-500) 16(100,-500) 17(0,-600) 18(100,-700) 19(100,-600) 20(200,-700) 21(200,-600) 22(300,-700) 23(300,-600) 24(400,-700) 25(400,-600) 26(500,-700) 27(500,-600) 28(600,-700) 29(700,-600) 30(600,-600) 31(700,-500) 32(600,-500) 33(700,-400) 34(600,-400) 35(700,-300) 36(600,-300) 37(700,-200) 38(600,-200) 39(700,-100) 40(600,0) 41(600,-100) 42(500,0) 43(500,-100) 44(400,0)
  silkscreen extent -50,-750 750,50
PQFP208 [mm]
  oval 2.45x0.3 smd: 1(-11.004,10.307) 2(-11.004,9.807) 3(-11.004,9.307) 4(-11.004,8.807) 5(-11.004,8.307) 6(-11.004,7.807) 7(-11.004,7.307) 8(-11.004,6.807) 9(-11.004,6.307) 10(-11.004,5.807) 11(-11.004,5.307) 12(-11.004,4.807) 13(-11.004,4.307) 14(-11.004,3.807) 15(-11.004,3.307) 16(-11.004,2.807) 17(-11.004,2.307) 18(-11.004,1.807) 19(-11.004,1.307) 20(-11.004,0.807) 21(-11.004,0.307) 22(-11.004,-0.193) 23(-11.004,-0.693) 24(-11.004,-1.193) 25(-11.004,-1.693) 26(-11.004,-2.193) 27(-11.004,-2.693) 28(-11.004,-3.193) 29(-11.004,-3.693) 30(-11.004,-4.193) 31(-11.004,-4.693) 32(-11.004,-5.193) 33(-11.004,-5.693) 34(-11.004,-6.193) 35(-11.004,-6.693) 36(-11.004,-7.193) 37(-11.004,-7.693) 38(-11.004,-8.193) 39(-11.004,-8.693) 40(-11.004,-9.193) 41(-11.004,-9.693) 42(-11.004,-10.193) 43(-11.004,-10.693) 44(-11.004,-11.193) 45(-11.004,-11.693) 46(-11.004,-12.193) 47(-11.004,-12.693) 48(-11.004,-13.193) 49(-11.004,-13.693) 50(-11.004,-14.193) 51(-11.004,-14.693) 52(-11.004,-15.193) 105(19.446,-15.193) 106(19.446,-14.693) 107(19.446,-14.193) 108(19.446,-13.693) 109(19.446,-13.193) 110(19.446,-12.693) 111(19.446,-12.193) 112(19.446,-11.693) 113(19.446,-11.193) 114(19.446,-10.693) 115(19.446,-10.193) 116(19.446,-9.693) 117(19.446,-9.193) 118(19.446,-8.693) 119(19.446,-8.193) 120(19.446,-7.693) 121(19.446,-7.193) 122(19.446,-6.693) 123(19.446,-6.193) 124(19.446,-5.693) 125(19.446,-5.193) 126(19.446,-4.693) 127(19.446,-4.193) 128(19.446,-3.693) 129(19.446,-3.193) 130(19.446,-2.693) 131(19.446,-2.193) 132(19.446,-1.693) 133(19.446,-1.193) 134(19.446,-0.693) 135(19.446,-0.193) 136(19.446,0.307) 137(19.446,0.807) 138(19.446,1.307) 139(19.446,1.807) 140(19.446,2.307) 141(19.446,2.807) 142(19.446,3.307) 143(19.446,3.807) 144(19.446,4.307) 145(19.446,4.807) 146(19.446,5.307) 147(19.446,5.807) 148(19.446,6.307) 149(19.446,6.807) 150(19.446,7.307) 151(19.446,7.807) 152(19.446,8.307) 153(19.446,8.807) 154(19.446,9.307) 155(19.446,9.807) 156(19.446,10.307)
  oval 0.3x2.45 smd: 53(-8.529,-17.668) 54(-8.029,-17.668) 55(-7.529,-17.668) 56(-7.029,-17.668) 57(-6.529,-17.668) 58(-6.029,-17.668) 59(-5.529,-17.668) 60(-5.029,-17.668) 61(-4.529,-17.668) 62(-4.029,-17.668) 63(-3.529,-17.668) 64(-3.029,-17.668) 65(-2.529,-17.668) 66(-2.029,-17.668) 67(-1.529,-17.668) 68(-1.029,-17.668) 69(-0.529,-17.668) 70(-0.029,-17.668) 71(0.471,-17.668) 72(0.971,-17.668) 73(1.471,-17.668) 74(1.971,-17.668) 75(2.471,-17.668) 76(2.971,-17.668) 77(3.471,-17.668) 78(3.971,-17.668) 79(4.471,-17.668) 80(4.971,-17.668) 81(5.471,-17.668) 82(5.971,-17.668) 83(6.471,-17.668) 84(6.971,-17.668) 85(7.471,-17.668) 86(7.971,-17.668) 87(8.471,-17.668) 88(8.971,-17.668) 89(9.471,-17.668) 90(9.971,-17.668) 91(10.471,-17.668) 92(10.971,-17.668) 93(11.471,-17.668) 94(11.971,-17.668) 95(12.471,-17.668) 96(12.971,-17.668) 97(13.471,-17.668) 98(13.971,-17.668) 99(14.471,-17.668) 100(14.971,-17.668) 101(15.471,-17.668) 102(15.971,-17.668) 103(16.471,-17.668) 104(16.971,-17.668) 157(16.971,12.782) 158(16.471,12.782) 159(15.971,12.782) 160(15.471,12.782) 161(14.971,12.782) 162(14.471,12.782) 163(13.971,12.782) 164(13.471,12.782) 165(12.971,12.782) 166(12.471,12.782) 167(11.971,12.782) 168(11.471,12.782) 169(10.971,12.782) 170(10.471,12.782) 171(9.971,12.782) 172(9.471,12.782) 173(8.971,12.782) 174(8.471,12.782) 175(7.971,12.782) 176(7.471,12.782) 177(6.971,12.782) 178(6.471,12.782) 179(5.971,12.782) 180(5.471,12.782) 181(4.971,12.782) 182(4.471,12.782) 183(3.971,12.782) 184(3.471,12.782) 185(2.971,12.782) 186(2.471,12.782) 187(1.971,12.782) 188(1.471,12.782) 189(0.971,12.782) 190(0.471,12.782) 191(-0.029,12.782) 192(-0.529,12.782) 193(-1.029,12.782) 194(-1.529,12.782) 195(-2.029,12.782) 196(-2.529,12.782) 197(-3.029,12.782) 198(-3.529,12.782) 199(-4.029,12.782) 200(-4.529,12.782) 201(-5.029,12.782) 202(-5.529,12.782) 203(-6.029,12.782) 204(-6.529,12.782) 205(-7.029,12.782) 206(-7.529,12.782) 207(-8.029,12.782) 208(-8.529,12.782)
  silkscreen extent -9.28,-15.97 17.7,11.08
PSOP20 [mm]
  oval 0.4x1.8 smd: 1(0,0) 2(0.65,0) 3(1.3,0) 4(1.95,0) 5(2.6,0) 6(3.25,0) 7(3.9,0) 8(4.55,0) 9(5.2,0) 10(5.85,0) 11(5.85,5.95) 12(5.2,5.95) 13(4.55,5.95) 14(3.9,5.95) 15(3.25,5.95) 16(2.6,5.95) 17(1.95,5.95) 18(1.3,5.95) 19(0.65,5.95) 20(0,5.95)
  silkscreen extent -0.4,1.4 6.3,4.6
RESC6332 [mm] "Chip Resistor, Body 6.3x3.2mm, IPC High Density"
  rect 1.1x3.3 smd: 1(-2.85,0) 2(2.85,0)
  silkscreen extent -1.9,-1.55 1.9,1.55, body extent -3.22,-1.68 3.22,1.68, height 0.9
SI51070 [mil]
  rect 60x60 hole 35: 1(350,100)
  round 60 hole 35: 2(300,0) 3(250,100) 4(200,0) 5(150,100) 6(100,0) 7(50,100) 8(0,0)
  round 60 hole 40: 9(390,290) 10(290,290) 11(60,290) 12(-40,290)
  round 80 hole 63: ""(-132,-130) ""(482,-130)
  round 150 hole 125: ""(-50,-250) ""(400,-250)
  silkscreen extent -140,-675 485,355
SIMM30 [mil]
  rect 62x62 hole 42: 1(0,0)
  round 62 hole 42: 2(100,0) 3(200,0) 4(300,0) 5(400,0) 6(500,0) 7(600,0) 8(700,0) 9(800,0) 10(900,0) 11(1000,0) 12(1100,0) 13(1200,0) 14(1300,0) 15(1400,0) 16(1500,0) 17(1600,0) 18(1700,0) 19(1800,0) 20(1900,0) 21(2000,0) 22(2100,0) 23(2200,0) 24(2300,0) 25(2400,0) 26(2500,0) 27(2600,0) 28(2700,0) 29(2800,0) 30(2900,0)
  round 85 hole 70: ""(-375,0)
  round 106 hole 92: ""(3275,0)
  silkscreen extent -455,-150 3350,150
SIP8 [mil]
  rect 60x60 hole 40: 1(0,0)
  round 60 hole 40: 2(100,0) 3(200,0) 4(300,0) 5(400,0) 6(500,0) 7(600,0) 8(700,0)
  silkscreen extent -50,-50 750,50
SJ1-352 [mm]
  round 1.6 hole 1.2: A(0,-10) B(0,-7.5) C(0,-2.5) D(0,0) E(5,-5) ""(0,-5) ""(5,0) ""(5,-10) ""(7.5,-10) ""(7.5,0)
  silkscreen extent -2,-11 9.5,1
SMD-1206 [mm] "Chip Inductor, 2-Leads, Body 3.2x1.6x1.3 mm"
  rect 1.35x1.2 smd: 1(-1.675,0) 2(1.675,0)
  silkscreen extent -0.35,-0.8 0.35,0.8, body extent -1.6,-0.8 1.6,0.8, height 1.3
SOT23 [mm] "For DMG3420U"
  rect 0.8x0.9 smd: D(0,0) G(-0.95,-2) S(0.95,-2)
SSOP44.400 [mm]
  oval 2x0.55 smd: 1(0,0) 2(0,-0.8) 3(0,-1.6) 4(0,-2.4) 5(0,-3.2) 6(0,-4) 7(0,-4.8) 8(0,-5.6) 9(0,-6.4) 10(0,-7.2) 11(0,-8) 12(0,-8.8) 13(0,-9.6) 14(0,-10.4) 15(0,-11.2) 16(0,-12) 17(0,-12.8) 18(0,-13.6) 19(0,-14.4) 20(0,-15.2) 21(0,-16) 22(0,-16.8) 23(12.448,-16.8) 24(12.448,-16) 25(12.448,-15.2) 26(12.448,-14.4) 27(12.448,-13.6) 28(12.448,-12.8) 29(12.448,-12) 30(12.448,-11.2) 31(12.448,-10.4) 32(12.448,-9.6) 33(12.448,-8.8) 34(12.448,-8) 35(12.448,-7.2) 36(12.448,-6.4) 37(12.448,-5.6) 38(12.448,-4.8) 39(12.448,-4) 40(12.448,-3.2) 41(12.448,-2.4) 42(12.448,-1.6) 43(12.448,-0.8) 44(12.448,0)
  silkscreen extent 1.4,-17.27 11.05,0.51
TI-PW16_M [mm] "SOP, 16-Leads, Body 5x4.4mm, Pitch 0.65mm, IPC Low Density"
  oval 2x0.35 smd: 1(-2.9,2.275) 2(-2.9,1.625) 3(-2.9,0.975) 4(-2.9,0.325) 5(-2.9,-0.325) 6(-2.9,-0.975) 7(-2.9,-1.625) 8(-2.9,-2.275) 9(2.9,-2.275) 10(2.9,-1.625) 11(2.9,-0.975) 12(2.9,-0.325) 13(2.9,0.325) 14(2.9,0.975) 15(2.9,1.625) 16(2.9,2.275)
  silkscreen extent -3.02,-2.55 1.5,3.13, body extent -2.25,-2.55 2.25,2.55, height 1.2
TO-220 [mil]
  round 125 hole 125: 0(100,700)
  rect 62x62 hole 40: 1(0,0) 2(100,0) 3(200,0)
  silkscreen extent -100,60 300,800
TSSOP48 [mm]
  oval 0.3x1.9 smd: 1(0,0) 2(0.5,0) 3(1,0) 4(1.5,0) 5(2,0) 6(2.5,0) 7(3,0) 8(3.5,0) 9(4,0) 10(4.5,0) 11(5,0) 12(5.5,0) 13(6,0) 14(6.5,0) 15(7,0) 16(7.5,0) 17(8,0) 18(8.5,0) 19(9,0) 20(9.5,0) 21(10,0) 22(10.5,0) 23(11,0) 24(11.5,0) 25(11.5,7.4) 26(11,7.4) 27(10.5,7.4) 28(10,7.4) 29(9.5,7.4) 30(9,7.4) 31(8.5,7.4) 32(8,7.4) 33(7.5,7.4) 34(7,7.4) 35(6.5,7.4) 36(6,7.4) 37(5.5,7.4) 38(5,7.4) 39(4.5,7.4) 40(4,7.4) 41(3.5,7.4) 42(3,7.4) 43(2.5,7.4) 44(2,7.4) 45(1.5,7.4) 46(1,7.4) 47(0.5,7.4) 48(0,7.4)
  silkscreen extent -0.4,1.4 11.9,6.1

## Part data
C1 C2 C3 C4 C5 C6 C7 C8 C9 C10 C11 C12 C13 C14 C15 C16 C17 C18 C19 C20 C21 C22 C23 C24 C25 C26 C27 C28 C29 C30 C31 C32 C33 C34 C36 C37 C38 C39 C40 C41 C42 C43 C44 C45 C46 C47 C48 C49 C50 C51 C52 C53 C54 C56 C57 C59 C60 C61 C62 C63 C64 C65 C66 C67 C68 C69 C70 C71 C72 C73 C74 C75 C76 C77 C78 C79 C81 C82 C83 C84 C85 C86 C87 C88 C89 C90 C91 C92 C93: library part "Cap Semi", "Capacitor (Semiconductor SIM Model)"
DISP1: library part SYM-1539121-1
J1: "MagJack SI-50170 Ethernet Jack with LEDs"
J2 J3: library part "PHONEJACK STEREO SW", "3.5mm Stereo Jack with Switches PHONEJACK STEREO SW"
J4: library part EJ508A, "EJ508A"
JTAG_SEL P3: "Header, 3-Pin"
K1: "Grayhill 4x4 Keypad"
L1 L2 L3 L4: "SMD EMI Suppression Ferrite Bead WE-CBF, Z = 500 Ohm"
P1: "Header, 10-Pin, Dual row"
P2: "Header, 4-Pin"
P4 P6 P7: "Header, 8-Pin, Dual row"
P8: "Header, 4-Pin, Dual row"
Q1: "JFET Chopper, P-Channel - Depletion, 3-Pin SOT-23, Tape and Reel", Manufacturer="On Semiconductor", Supplier Part Number 1=MMBFJ175LT1OSCT-ND
Q2: library part DMG3420
R1 R2 R3 R4 R5 R6 R7 R8 R9 R10 R11 R12 R13 R14 R15 R16 R17 R18 R19 R20 R21 R22 R23 R24 R25 R26 R27 R28 R29 R30 R31 R32 R33 R34 R35 R36 R37 R38 R39 R40 R41 R42 R43 R44 R45 R46 R47 R48 R49 R50 R51 R52 R53 R54 R55 R56 R57 R59 R63 R64 R65 R66 R67: "Resistor"
R58 R60 R61 R62: library part Res3, "MCR100JZHJ2R2"
REG_1V8 REG_3V REG_3V3 REG_5V: library part LM1086, "1.5A Low Dropout Positive Regulator"
U1: "Atmel ARM"
U2 U4 U8 U18 U19 U21: "16-Bit Bus Transceiver"
U3: "Maxim uP Supervisory Circuit"
U5: "In-System Programmable High Density CPLD"
U6: library part IDT71V016, "64K x 16 3.3V Static CMOS RAM"
U7: library part 29LV040, "4 Megabit (512K x 8) CMOS Uniform Sector Flash Memory"
U13: "20-Key Encoder"
U15: "I2C Serial EEPROM"
U16: "PHYTER - Single Port 10/100 Mb/s Ethernet Physical Layer Transceiver"
U17: "PCM Codec"
U20: "1M x 8 DRAM SIMM"
X1 X2 X3: library part CRYSTAL, "Crystal"

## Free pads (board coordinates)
  round 250 hole 201: 2(300,6200) 3(6400,6200) 4(6400,300) 5(300,300)

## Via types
v1: diameter 30, hole 16, Top Layer to Bottom Layer, 461 vias

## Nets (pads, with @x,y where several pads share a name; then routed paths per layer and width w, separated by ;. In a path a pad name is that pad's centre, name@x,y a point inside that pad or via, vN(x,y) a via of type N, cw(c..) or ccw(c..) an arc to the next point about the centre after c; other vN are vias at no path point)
1V8: C5.2 C7.2 C9.2 C11.2 C13.2 C15.2 C17.2 C19.2 C72.2 R47.2 REG_1V8.2 U1.19 U1.28 U1.33 U1.37 U1.62 U1.116 U1.152 U1.188 | length 8729.7
  Top Layer w8: C72.2@937.85,1079 1005.06,1011.8 R47.2@1005.06,994 ; v1(2153,3254) 2153,3187 2150,3184 2264.71,3069.29 U1.28@2321.77,3069.29 2323.4,3067.66 2414.66,3067.66 2453,3106 ; C19.2@2155,2987.56 2168.91,2973.65 2195.24,2973.65 2195.59,2974 2254.41,2974 2254.76,2973.65 2318.99,2973.65 U1.33@2321.77,2970.87 2406.87,2970.87 2453,3017 ; U1.37@2321.77,2892.13 2324.55,2889.35 2398.35,2889.35 2453,2944 ; U1.19@2321.77,3246.46 2443.54,3246.46 v1(2453,3237) 2453,3174.77 2464,3163.77 2464,3142.23 2453,3131.23 2453,3106 ; U1.62@2596.38,2499.41 2597,2500.03 v1(2597,2658) ; v1(2645,2946) 2643,2944 2453,2944 ; v1(2812.91,3553.09) U1.188@2812.91,3698.23 ; v1(3384.56,2862) 3425.43,2862 3446.36,2841.07 3446.36,2839.54 3469.74,2816.17 3517.81,2816.17 U1.116@3520.59,2813.39 ; v1(3408.95,3522.05) U1.152@3520.59,3522.05 ; 2453,2944 2453,3017 ; 2453,3017 2453,3106
  Top Layer w20: 1906,2294 1906,2260.75 1924.75,2242 2062.25,2242 2081,2260.75 2081,2277 2200,2396 2200,2483.25 2218.75,2502 2301.64,2502 2387,2587.36 2387,2650 2443,2706 2549,2706 v1(2597,2658) 2652,2658 2687,2693 2687,2697.25 2798.75,2809 2979.99,2809 3012.99,2776 3021.48,2776 3022.48,2777 3048.99,2777 3049.99,2776 3171,2776 3201,2806 3277,2806 3333,2862 v1(3384.56,2862) 3257,2989.56 3257,3322 3408.95,3473.95 v1(3408.95,3522.05) 3333.9,3447 2919,3447 v1(2812.91,3553.09) 2812.91,3464.91 2665,3317 2575,3317 2453,3439 2453,3381.25 2463,3371.25 2463,3327.25 2444,3308.25 2444,3281.75 2453,3272.75 v1(2453,3237)
  Top Layer w30: REG_1V8.2@841,1064 922.85,1064 C72.2@937.85,1079 ; v1(1417,1953) v1(1417,2001) v1(1417,2046) 1417,2084 1672,2339 1861,2339 1906,2294
  Bottom Layer w8: C15.2@2017,3298.12 2107.88,3298.12 2152,3254 v1(2153,3254) ; C5.2@2452.44,3235 2453,3235 v1(2453,3237) ; v1(2645,2946) 2680.56,2946 C17.2@2719,2907.56 ; C9.2@2810,3552.56 2813.44,3552.56 v1(2812.91,3553.09) ; C11.2@3383.56,2861 v1(3384.56,2862) ; C7.2@3407.56,3523 3408,3523 v1(3408.95,3522.05)
  Bottom Layer w30: REG_1V8.2@841,1064 845.93,1064 1417,1635.07 v1(1417,1953) v1(1417,2001) ; v1@1415,1999 v1(1417,2001) ; v1(1417,2046) v1(1417,2001)
3V: C53.1 C54.1 C78.2 C79.2 DISP1.12 DISP1.18 R53.2 REG_3V.2 U9.16 U11.16 | length 5408.8
  Top Layer w8: C78.2@947.85,1743 947.85,1705.68 R53.2@1013.53,1640
  Top Layer w10: v1(685,4503.26) U9.16@623.57,4441.83 623.57,4276.32 DISP1.12@739.89,4160 DISP1.12@745,4154.89 ; v1(685,4624.74) U11.16@728.43,4668.17 ; 784,3532 784,4115.89 DISP1.12@745,4154.89 ; C79.2@815.44,4256 745,4185.56 DISP1.12@745,4154.89
  Top Layer w30: C78.2@947.85,1743 895,1743 REG_3V.2@842,1690 271,2261 271,3453 350,3532 784,3532 1046.93,3532 DISP1.18@1598.16,4083.23
  Bottom Layer w10: C53.1@667.44,4075 739.89,4147.45 DISP1.12@739.89,4160 ; C54.1@675,4691.44 675,4634.74 v1(685,4624.74) 686,4623.74 686,4504.26 v1(685,4503.26)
